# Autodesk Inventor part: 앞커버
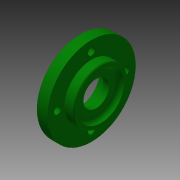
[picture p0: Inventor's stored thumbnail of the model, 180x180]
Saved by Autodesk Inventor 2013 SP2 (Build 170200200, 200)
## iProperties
Created: 2015-12
Part Number: 앞커버
Material: 알루미늄 6061
Document SubType Name: Modeling
Designer: mduedu
Density: 2.71 g/cm^3
Author: mduedu
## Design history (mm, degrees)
sketch "스케치1"
  geometry: L1 (0, 0)-(14, 0); L2 (14, 0)-(14, 17.5); L3 (14, 17.5)-(8, 17.5); L4 (8, 17.5)-(8, 28.5); L5 (8, 28.5)-(0, 28.5); L6 (0, 28.5)-(0, 0)
  constraints: 12 end point, 4 parallel, 1 horizontal, 1 perpendicular
  dimensions: "d0" = 14 distance between parallel lines of L2 L6; "d2" = 8 distance of L4.end L5.end; "d3" = 57 diameter of L5 L1; "d4" = 35 diameter of L3 L1
revolve "회전1" sketch "스케치1" stored, may be unused: angle "d5" = 90 deg
hole "구멍1" diameter "d8" = 30; stored, may be unused: countersink angle "d12" = 90 deg, drill point angle "d14" = 0 deg; dims "d6" = 10, "d7" = 10, "d9" = 6, "d10" = 4, "d11" = 2, "d13" = 3
hole "구멍2" diameter "d17" = 25; stored, may be unused: countersink angle "d21" = 90 deg, drill point angle "d23" = 0 deg; dims "d15" = 10, "d16" = 10, "d18" = 6, "d19" = 4, "d20" = 2, "d22" = 7.3
hole "구멍3" diameter "d26" = 16.5; stored, may be unused: countersink angle "d30" = 90 deg, drill point angle "d32" = 0 deg; dims "d24" = 10, "d25" = 10, "d27" = 6, "d28" = 4, "d29" = 2, "d31" = 7.3
fillet "모깎기1" dims "d33" = 0.3
chamfer "모따기1" distance "d34" = 1; stored, may be unused: second distance "d35" = 2, angle "d36" = 30 deg
fillet "모깎기2" dims "d37" = 3
fillet "모깎기3" dims "d38" = 2
chamfer "모따기2" distance "d39" = 0.5; stored, may be unused: second distance "d40" = 2, angle "d41" = 45 deg
sketch "스케치2" dims "d42" = 42
  geometry: 9 further points
  constraints: 3 coincident, 2 vertical alignment, 9 other
  dimensions: "d46" = 360 deg dimension on point (0, 0) point (0, 21) (derived)
sketch "스케치3" dims "d57" = 44
  geometry: C1 r 13.077 at (0, 0) reference; C2 r 26.5 at (0, 0) reference; 5 further points
  constraints: 3 horizontal alignment, 1 coincident, 1 vertical alignment, 2 other
hole "구멍4" sketch "스케치3" at (-22, 0), (0, -22), (22, 0), (0, 22) diameter "d50" = 4.5; stored, may be unused: countersink angle "d54" = 90 deg, drill point angle "d56" = 0 deg; dims "d51" = 6, "d52" = 8, "d53" = 4.6, "d55" = 8
node "솔리드1"
